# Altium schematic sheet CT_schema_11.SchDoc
size 274 x 160 mm
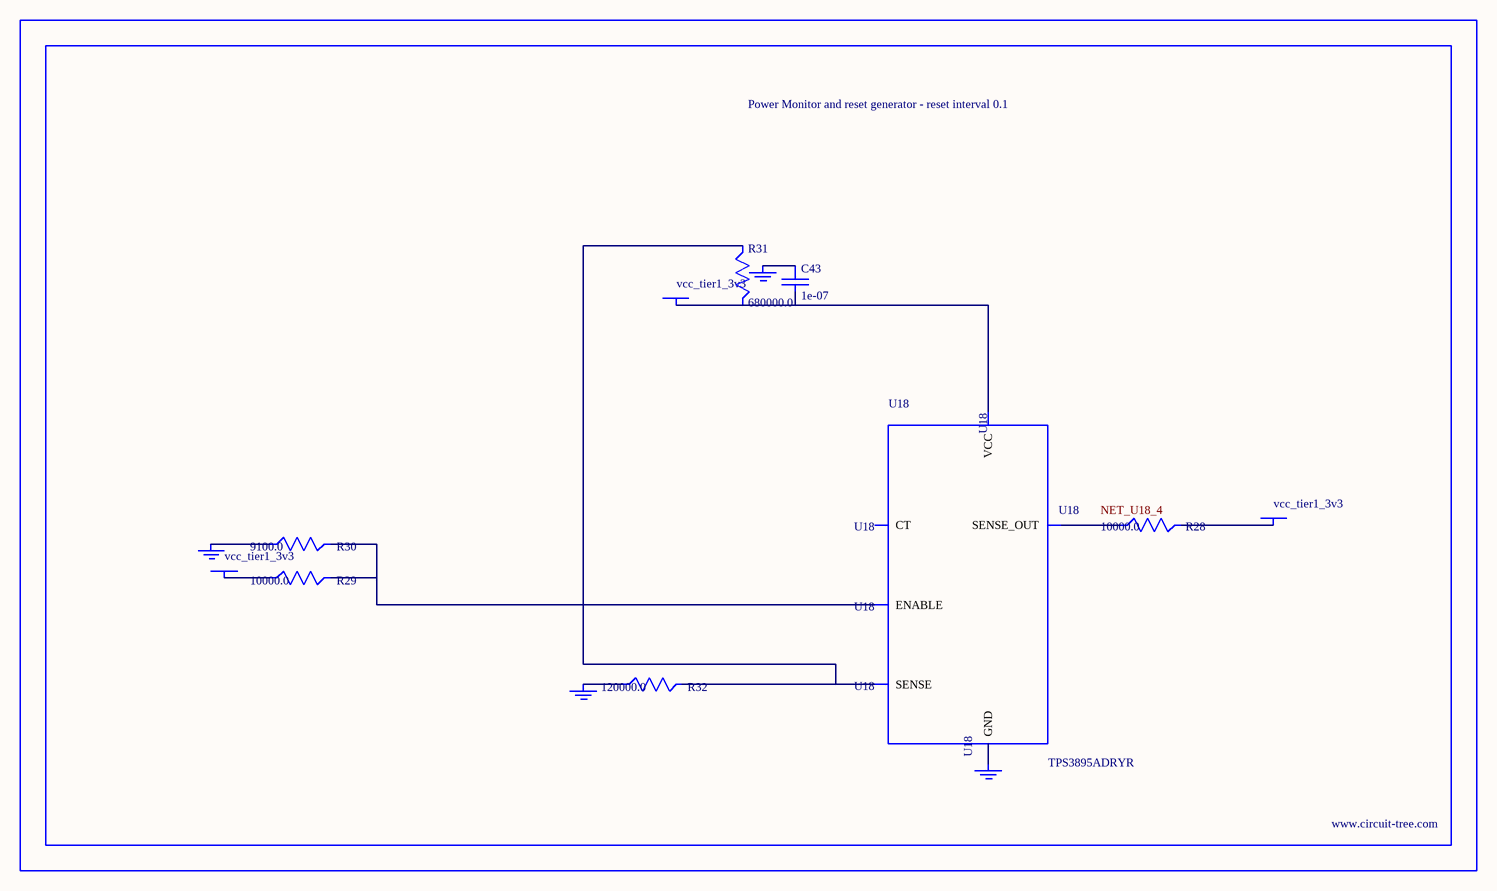
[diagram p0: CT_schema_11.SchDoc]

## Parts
BORDER10  (no value)
C43  1e-07  [C0402]
GND_INSTANCE_10_0  (no value)
GND_INSTANCE_10_1  (no value)
GND_INSTANCE_10_2  (no value)
GND_INSTANCE_10_3  (no value)
POWER_INSTANCE_10_0  vcc_tier1_3v3
POWER_INSTANCE_10_1  vcc_tier1_3v3
POWER_INSTANCE_10_2  vcc_tier1_3v3
R28  10000.0  [R0603]
R29  10000.0  [R0603]
R30  9100.0  [R0603]
R31  680000.0  [R0603]
R32  120000.0  [R0603]
U18  TPS3895ADRYR  [SON-6]

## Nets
NetC43_1: C43.1 GND_INSTANCE_10_2.0(GND)
NetC43_2: C43.2 POWER_INSTANCE_10_2.0(PWR) R31.2 U18.6(VCC)
NetGND_INSTANCE_10_0_0: GND_INSTANCE_10_0.0(GND) R30.1
NetGND_INSTANCE_10_1_0: GND_INSTANCE_10_1.0(GND) R32.1
NetGND_INSTANCE_10_3_0: GND_INSTANCE_10_3.0(GND) U18.2(GND)
NetPOWER_INSTANCE_10_0_0: POWER_INSTANCE_10_0.0(PWR) R29.1
NetPOWER_INSTANCE_10_1_0: POWER_INSTANCE_10_1.0(PWR) R28.2
NetR28_1: R28.1 U18.4(SENSE_OUT)
NetR29_2: R29.2 R30.2 U18.1(ENABLE)
NetR31_1: R31.1 R32.2 U18.3(SENSE)

Not connected (* = marked no-connect by the designer): U18 5(CT)

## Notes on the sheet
- Labels drawn without touching a wire or pin: NET_U18_4

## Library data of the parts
BORDER10 = BORDER_PAGE10
C43 = C0402C104K3RACTU
GND_INSTANCE_10_0-GND_INSTANCE_10_3 = GND
POWER_INSTANCE_10_0-POWER_INSTANCE_10_2 = PWR
R28 R29 = RC0603JR-0710KL
R30 = RC0603JR-079K1L
R31 = RC0603JR-07680KL
R32 = RC0603JR-07120KL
